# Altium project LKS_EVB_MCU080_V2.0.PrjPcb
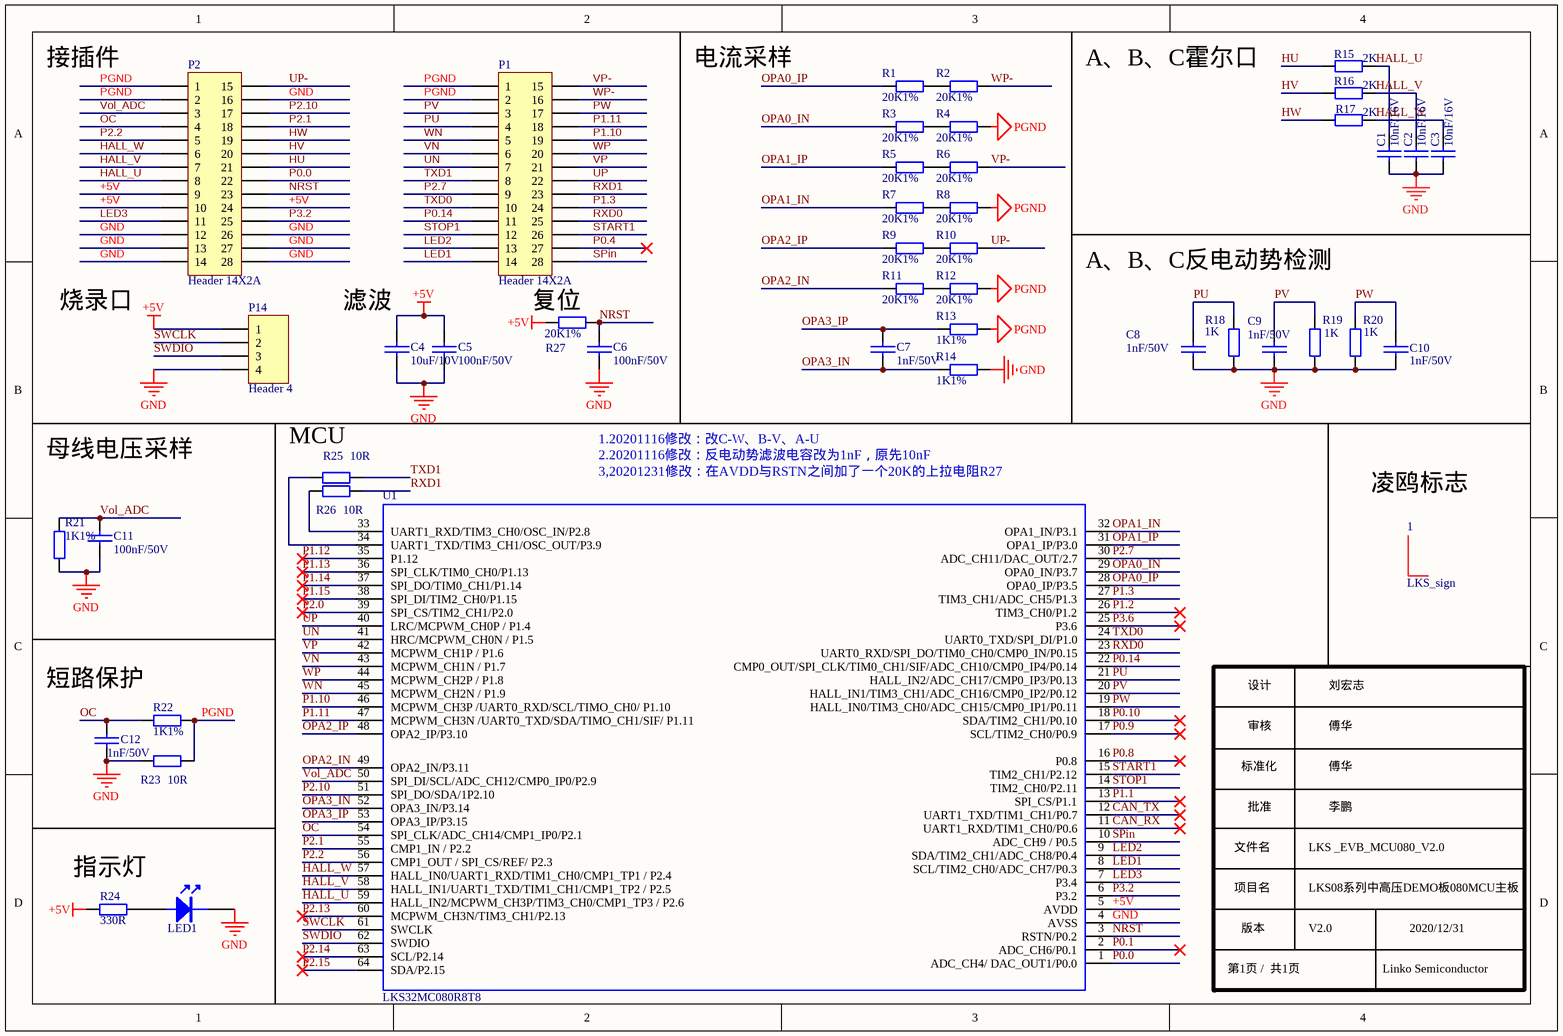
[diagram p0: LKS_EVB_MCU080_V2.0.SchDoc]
1 sheet, 45 parts. Net scope: global (net labels, ports and power ports of the same name join across sheets).
Board file: LKS_EVB_MCU080_V2.0.PcbDoc

## Sheet LKS_EVB_MCU080_V2.0.SchDoc
size A4; SheetNumber: 1; SheetTotal: 1

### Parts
1  LKS_sign  [LKS_LOGO2]
C1  10nF/16V  [0603C]
C2  10nF/16V  [0603C]
C3  10nF/16V  [0603C]
C4  10uF/10V  [0603C]
C5  100nF/50V  [0603C]
C6  100nF/50V  [0603C]
C7  1nF/50V  [0603C]
C8  1nF/50V  [0603C]
C9  1nF/50V  [0603C]
C10  1nF/50V  [0603C]
C11  100nF/50V  [0603C]
C12  1nF/50V  [0603C]
LED1  LED  [LED 0603R]  (value not drawn)
P1  Header 14X2A  [HDR2X14_CEN]
P2  Header 14X2A  [HDR2X14_CEN]
P14  Header 4  [HDR1X4]
R1  20K1%  [0603R]
R2  20K1%  [0603R]
R3  20K1%  [0603R]
R4  20K1%  [0603R]
R5  20K1%  [0603R]
R6  20K1%  [0603R]
R7  20K1%  [0603R]
R8  20K1%  [0603R]
R9  20K1%  [0603R]
R10  20K1%  [0603R]
R11  20K1%  [0603R]
R12  20K1%  [0603R]
R13  1K1%  [0603R]
R14  1K1%  [0603R]
R15  2K  [0603R]
R16  2K  [0603R]
R17  2K  [0603R]
R18  1K  [0603R]
R19  1K  [0603R]
R20  1K  [0603R]
R21  1K1%  [0603R]
R22  1K1%  [0603R]
R23  10R  [0603R]
R24  330R  [0603R]
R25  10R  [0603R]
R26  10R  [0603R]
R27  20K1%  [0603R]
U1  LKS32MC080R8T8  [LQFP64]

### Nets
+5V: C4.2 C5.2 P2.9 P2.10 P2.24 P14.1 R24.1 R27.2 U1.5(AVDD)
GND: C1.2 C2.2 C3.2 C4.1 C5.1 C6.2 C8.2 C9.2 C10.2 C11.1 C12.1 LED1.2(K) P2.12 P2.13 P2.14 P2.16 P2.26 P2.27 P2.28 P14.4 R14.1 R18.2 R19.2 R20.2 R21.1 R23.2 U1.4(AVSS)
PGND: P1.1 P1.2 P2.1 P2.2 R4.1 R8.1 R12.1 R13.1 R22.2 R23.1
CAN_RX: U1.11(UART1_RXD/TIM1_CH0/P0.6)
CAN_TX: U1.12(UART1_TXD/TIM1_CH1/P0.7)
HALL_U: C1.1 P2.8 R15.2 U1.59(HALL_IN2/MCPWM_CH3P/TIM3_CH0/CMP1_TP3_/_P2.6)
HALL_V: C2.1 P2.7 R16.2 U1.58(HALL_IN1/UART1_TXD/TIM1_CH1/CMP1_TP2_/_P2.5)
HALL_W: C3.1 P2.6 R17.2 U1.57(HALL_IN0/UART1_RXD/TIM1_CH0/CMP1_TP1_/_P2.4)
HU: P2.21 R15.1
HV: P2.20 R16.1
HW: P2.19 R17.1
LED1: P1.14 U1.8(SCL/TIM2_CH0/ADC_CH7/P0.3)
LED2: P1.13 U1.9(SDA/TIM2_CH1/ADC_CH8/P0.4)
LED3: P2.11 U1.7(P3.4)
NRST: C6.1 P2.23 R27.1 U1.3(RSTN/P0.2)
OC: C12.2 P2.4 R22.1 U1.54(SPI_CLK/ADC_CH14/CMP1_IP0/P2.1)
OPA0_IN: R3.2 U1.29(OPA0_IN/P3.7)
OPA0_IP: R1.2 U1.28(OPA0_IP/P3.5)
OPA1_IN: R7.2 U1.32(OPA1_IN/P3.1)
OPA1_IP: R5.2 U1.31(OPA1_IP/P3.0)
OPA2_IN: R11.2 U1.49(OPA2_IN/P3.11)
OPA2_IP: R9.2 U1.48(OPA2_IP/P3.10)
OPA3_IN: C7.2 R14.2 U1.52(OPA3_IN/P3.14)
OPA3_IP: C7.1 R13.2 U1.53(OPA3_IP/P3.15)
P0.0: P2.22 U1.1(ADC_CH4/_DAC_OUT1/P0.0)
P0.1: U1.2(ADC_CH6/P0.1)
P0.4: P1.27
P0.8: U1.16(P0.8)
P0.9: U1.17(SCL/TIM2_CH0/P0.9)
P0.10: U1.18(SDA/TIM2_CH1/P0.10)
P0.14: P1.11 U1.22(CMP0_OUT/SPI_CLK/TIM0_CH1/SIF/ADC_CH10/CMP0_IP4/P0.14)
P1.1: U1.13(SPI_CS/P1.1)
P1.2: U1.26(TIM3_CH0/P1.2)
P1.3: P1.24 U1.27(TIM3_CH1/ADC_CH5/P1.3)
P1.10: P1.19 U1.46(MCPWM_CH3P_/UART0_RXD/SCL/TIMO_CH0/_P1.10)
P1.11: P1.18 U1.47(MCPWM_CH3N_/UART0_TXD/SDA/TIMO_CH1/SIF/_P1.11)
P1.12: U1.35(P1.12)
P1.13: U1.36(SPI_CLK/TIM0_CH0/P1.13)
P1.14: U1.37(SPI_DO/TIM0_CH1/P1.14)
P1.15: U1.38(SPI_DI/TIM2_CH0/P1.15)
P2.0: U1.39(SPI_CS/TIM2_CH1/P2.0)
P2.1: P2.18 U1.55(CMP1_IN_/_P2.2)
P2.2: P2.5 U1.56(CMP1_OUT_/_SPI_CS/REF/_P2.3)
P2.7: P1.9 U1.30(ADC_CH11/DAC_OUT/2.7)
P2.10: P2.17 U1.51(SPI_DO/SDA/1P2.10)
P2.13: U1.60(MCPWM_CH3N/TIM3_CH1/P2.13)
P2.14: U1.63(SCL/P2.14)
P2.15: U1.64(SDA/P2.15)
P3.2: P2.25 U1.6(P3.2)
P3.6: U1.25(P3.6)
PU: C8.1 P1.4 R18.1 U1.21(HALL_IN2/ADC_CH17/CMP0_IP3/P0.13)
PV: C9.1 P1.3 R19.1 U1.20(HALL_IN1/TIM3_CH1/ADC_CH16/CMP0_IP2/P0.12)
PW: C10.1 P1.17 R20.1 U1.19(HALL_IN0/TIM3_CH0/ADC_CH15/CMP0_IP1/P0.11)
RXD0: P1.25 U1.23(UART0_RXD/SPI_DO/TIM0_CH0/CMP0_IN/P0.15)
RXD1: P1.23 R26.2
SPin: P1.28 U1.10(ADC_CH9_/_P0.5)
START1: P1.26 U1.15(TIM2_CH1/P2.12)
STOP1: P1.12 U1.14(TIM2_CH0/P2.11)
SWCLK: P14.2 U1.61(SWCLK)
SWDIO: P14.3 U1.62(SWDIO)
TXD0: P1.10 U1.24(UART0_TXD/SPI_DI/P1.0)
TXD1: P1.8 R25.1
UN: P1.7 U1.41(HRC/MCPWM_CH0N_/_P1.5)
UP: P1.22 U1.40(LRC/MCPWM_CH0P_/_P1.4)
UP-: P2.15 R10.1
VN: P1.6 U1.43(MCPWM_CH1N_/_P1.7)
Vol_ADC: C11.2 P2.3 R21.2 U1.50(SPI_DI/SCL/ADC_CH12/CMP0_IP0/P2.9)
VP: P1.21 U1.42(MCPWM_CH1P_/_P1.6)
VP-: P1.15 R6.1
WN: P1.5 U1.45(MCPWM_CH2N_/_P1.9)
WP: P1.20 U1.44(MCPWM_CH2P_/_P1.8)
WP-: P1.16 R2.1
NetLED1_1: LED1.1(A) R24.2
NetR1_1: R1.1 R2.2
NetR3_1: R3.1 R4.2
NetR5_1: R5.1 R6.2
NetR7_1: R7.1 R8.2
NetR9_1: R9.1 R10.2
NetR11_1: R11.1 R12.2
NetR25_2: R25.2 U1.34(UART1_TXD/TIM3_CH1/OSC_OUT/P3.9)
NetR26_1: R26.1 U1.33(UART1_RXD/TIM3_CH0/OSC_IN/P2.8)

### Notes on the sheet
- 接插件
- 烧录口
- (near C4) 滤波
- (near R27) 复位
- 1.20201116修改：改C-W、B-V、A-U
- 母线电压采样
- 2.20201116修改：反电动势滤波电容改为1nF，原先10nF
- (near U1) 3,20201231修改：在AVDD与RSTN之间加了一个20K的上拉电阻R27
- (near 1) 凌鸥标志
- 短路保护
- 设计
- 刘宏志
- 标准化
- 审核
- 傅华
- 文件名
- 批准
- LKS _EVB_MCU080_V2.0
- 李鹏
- (near R24) 指示灯
- 项目名
- LKS08系列中高压DEMO板080MCU主板
- 第1页 /  共1页
- 版本
- V2.0
- Linko Semiconductor
- 2020/12/31
- Labels drawn without touching a wire or pin: A、B、C反电动势检测, A、B、C霍尔口, MCU, 电流采样

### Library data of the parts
C1-C3 C8-C10 = CAP: Capacitor
C4-C7 C11 C12 = C: Capacitor
LED1 = LED: LED_Light
P1 P2 = Header 14X2A: Header, 14-Pin, Dual row
P14 = Header 4: Header, 4-Pin
R1-R27 = Res: Resistor; Value: K
U1 = LKS080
